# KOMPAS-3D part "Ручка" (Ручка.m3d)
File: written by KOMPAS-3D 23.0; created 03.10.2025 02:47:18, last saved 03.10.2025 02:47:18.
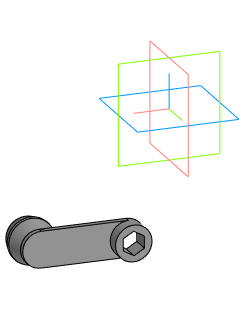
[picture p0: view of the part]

Document properties: Автор: Inspektor_Kot; Полное имя файла: I:\Autodesk Inventor Projects\ИМ-ИТ ЦД\Вариант 13\Ручка.m3d

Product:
- Part/product: Ручка

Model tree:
1. Эскиз:1  (with: Элемент выдавливания:1, Элемент выдавливания:5)
2. Элемент выдавливания:1
     Расстояние 2 = 10
3. Эскиз:2  (with: Элемент выдавливания:1)
4. Элемент выдавливания:2
     Расстояние 2 = 3
5. Эскиз:3  (with: Элемент выдавливания:1, Элемент выдавливания:2)
6. Элемент выдавливания:3
     Расстояние 1 = 10; Угол 1 = 15
7. Элемент выдавливания:4  (with: Элемент выдавливания:3)
     Расстояние 1 = 10; Угол 1 = -15
8. Скругление:1  (with: Элемент выдавливания:4)
     Радиус = 4

Referenced files in I:\Autodesk Inventor Projects\ИМ-ИТ ЦД\Вариант 13\: Стенд ДВС.a3d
